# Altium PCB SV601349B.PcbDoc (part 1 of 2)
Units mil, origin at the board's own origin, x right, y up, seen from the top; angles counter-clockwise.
Board outline 3013 x 3112 mil, 4 copper layers (TOP, GND, PWR, BOTTOM), stack 60.36 mil thick; 123 components, 67 nets, 345 pads, 132 vias.
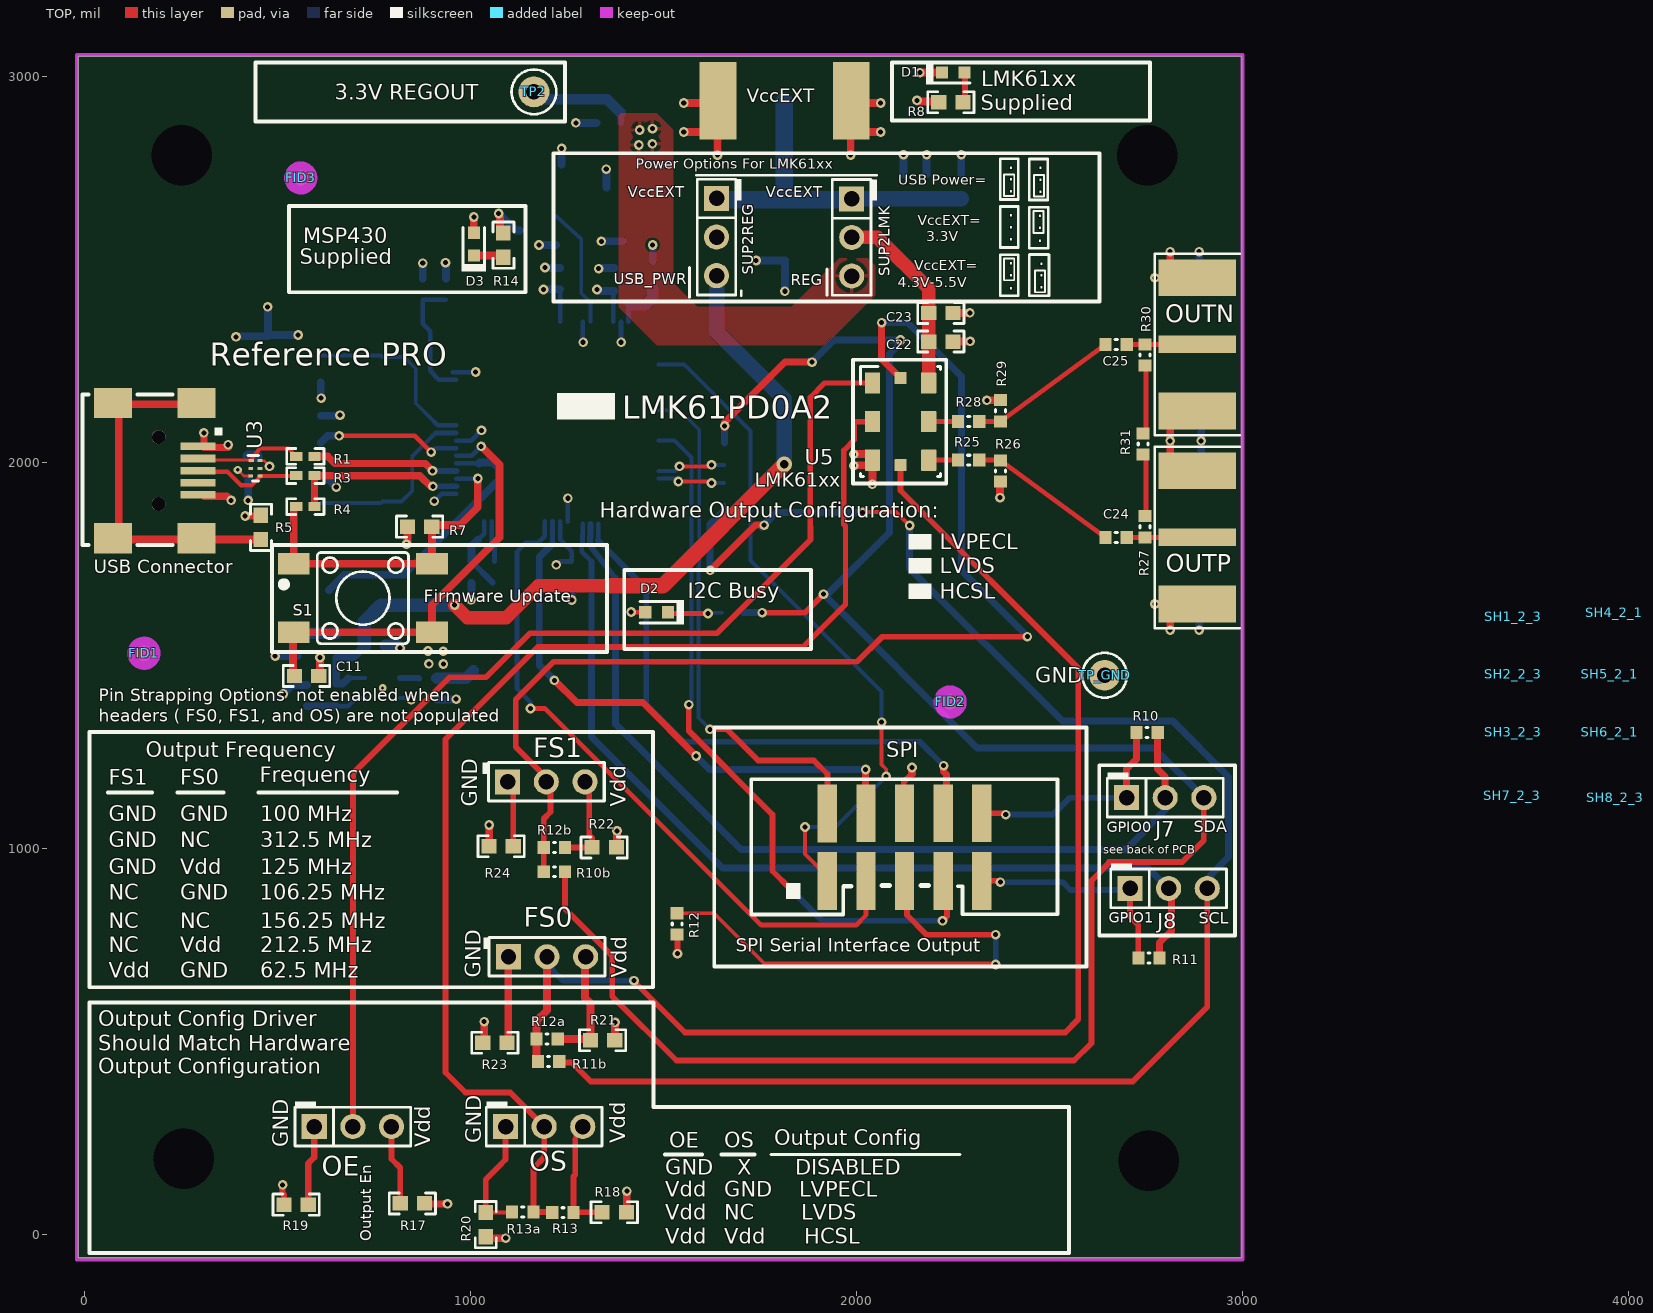
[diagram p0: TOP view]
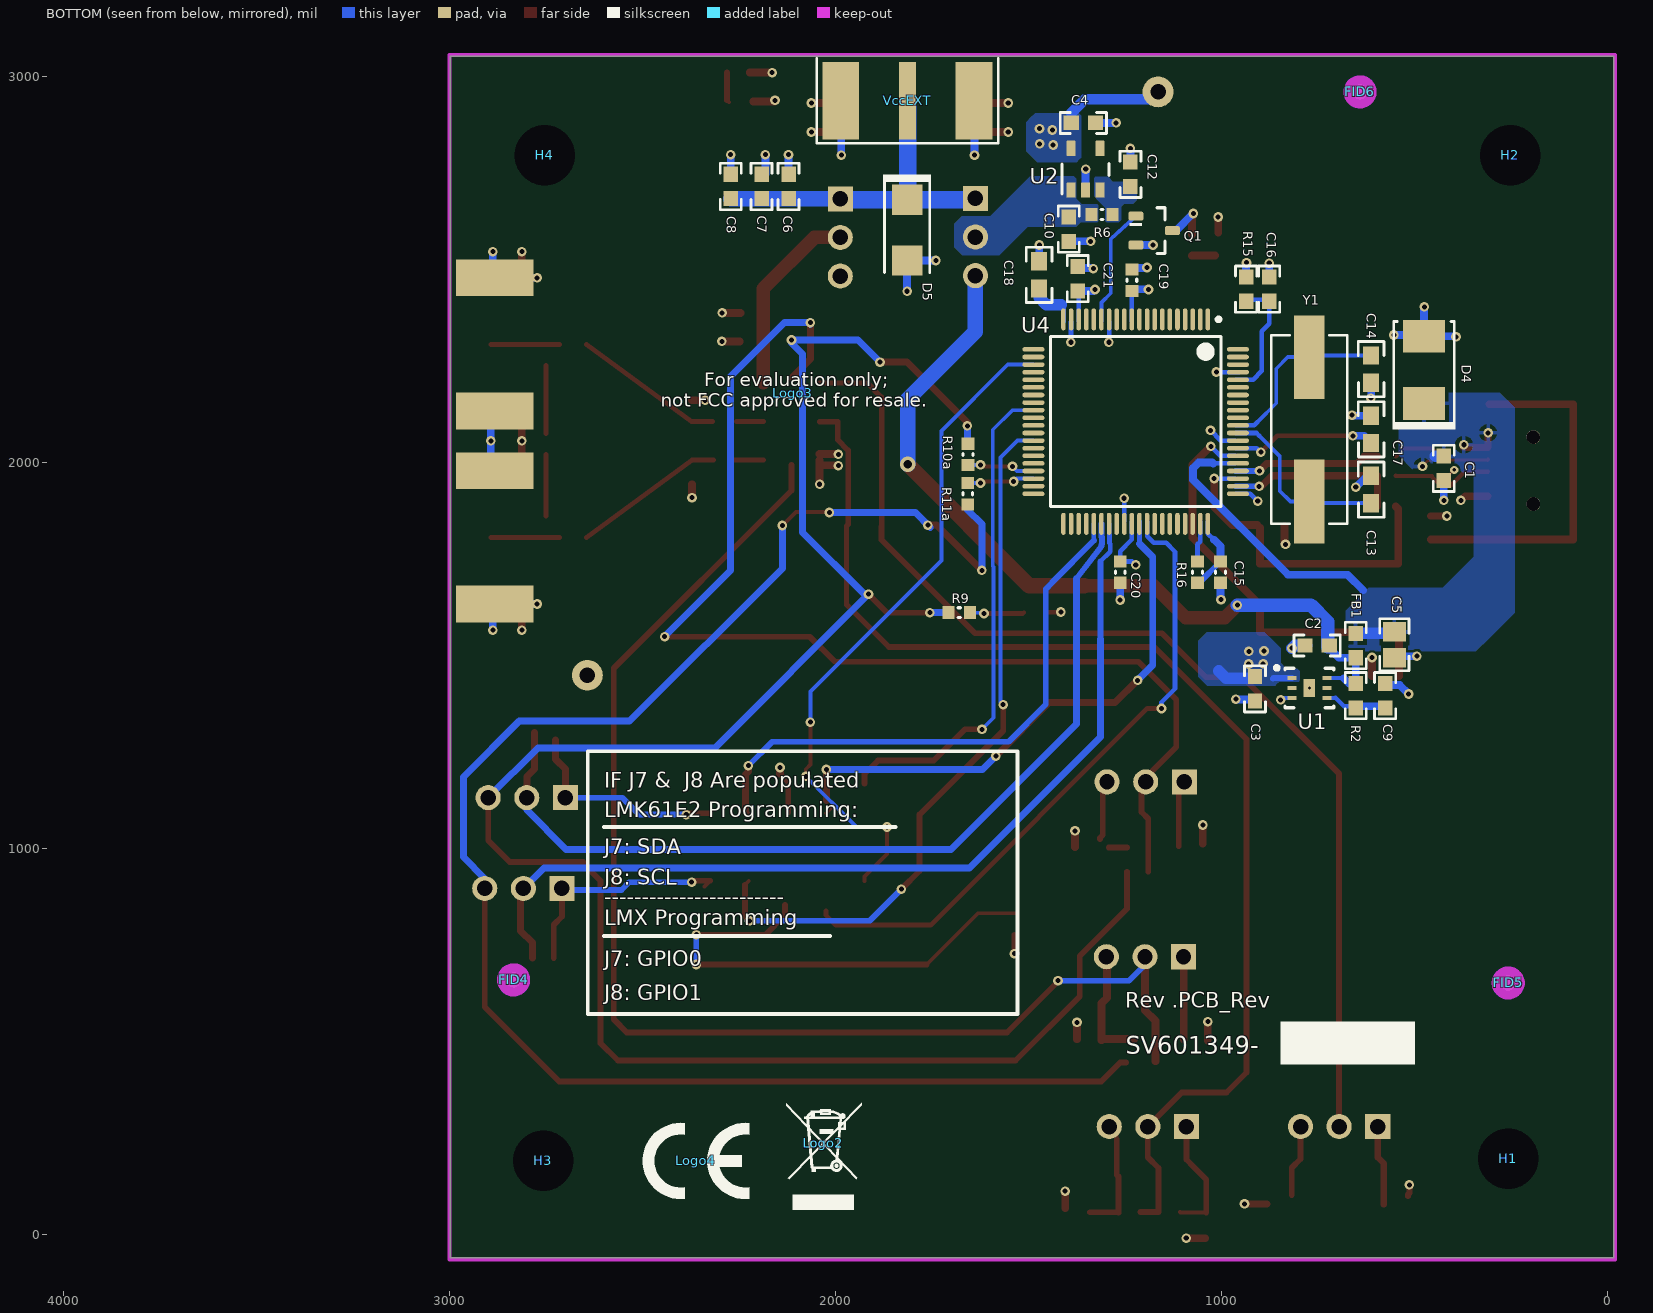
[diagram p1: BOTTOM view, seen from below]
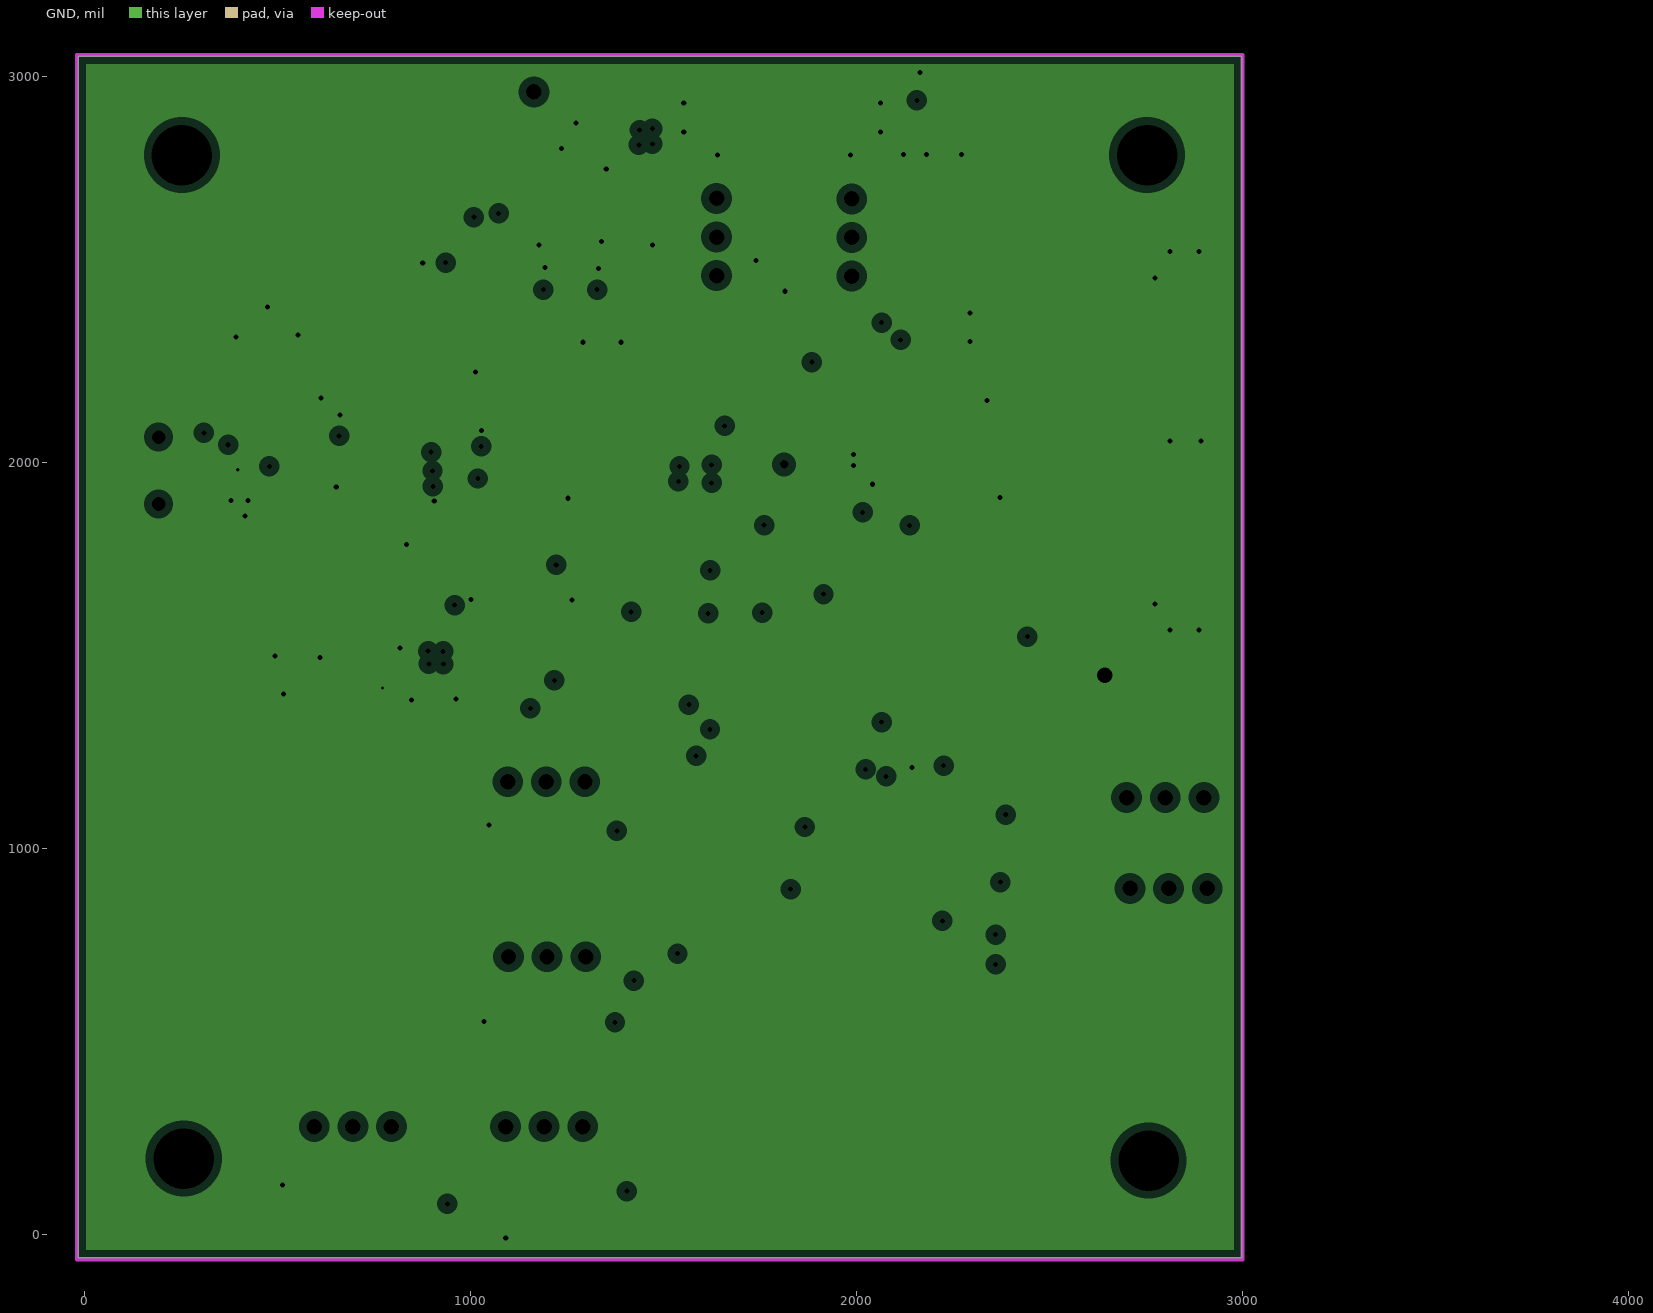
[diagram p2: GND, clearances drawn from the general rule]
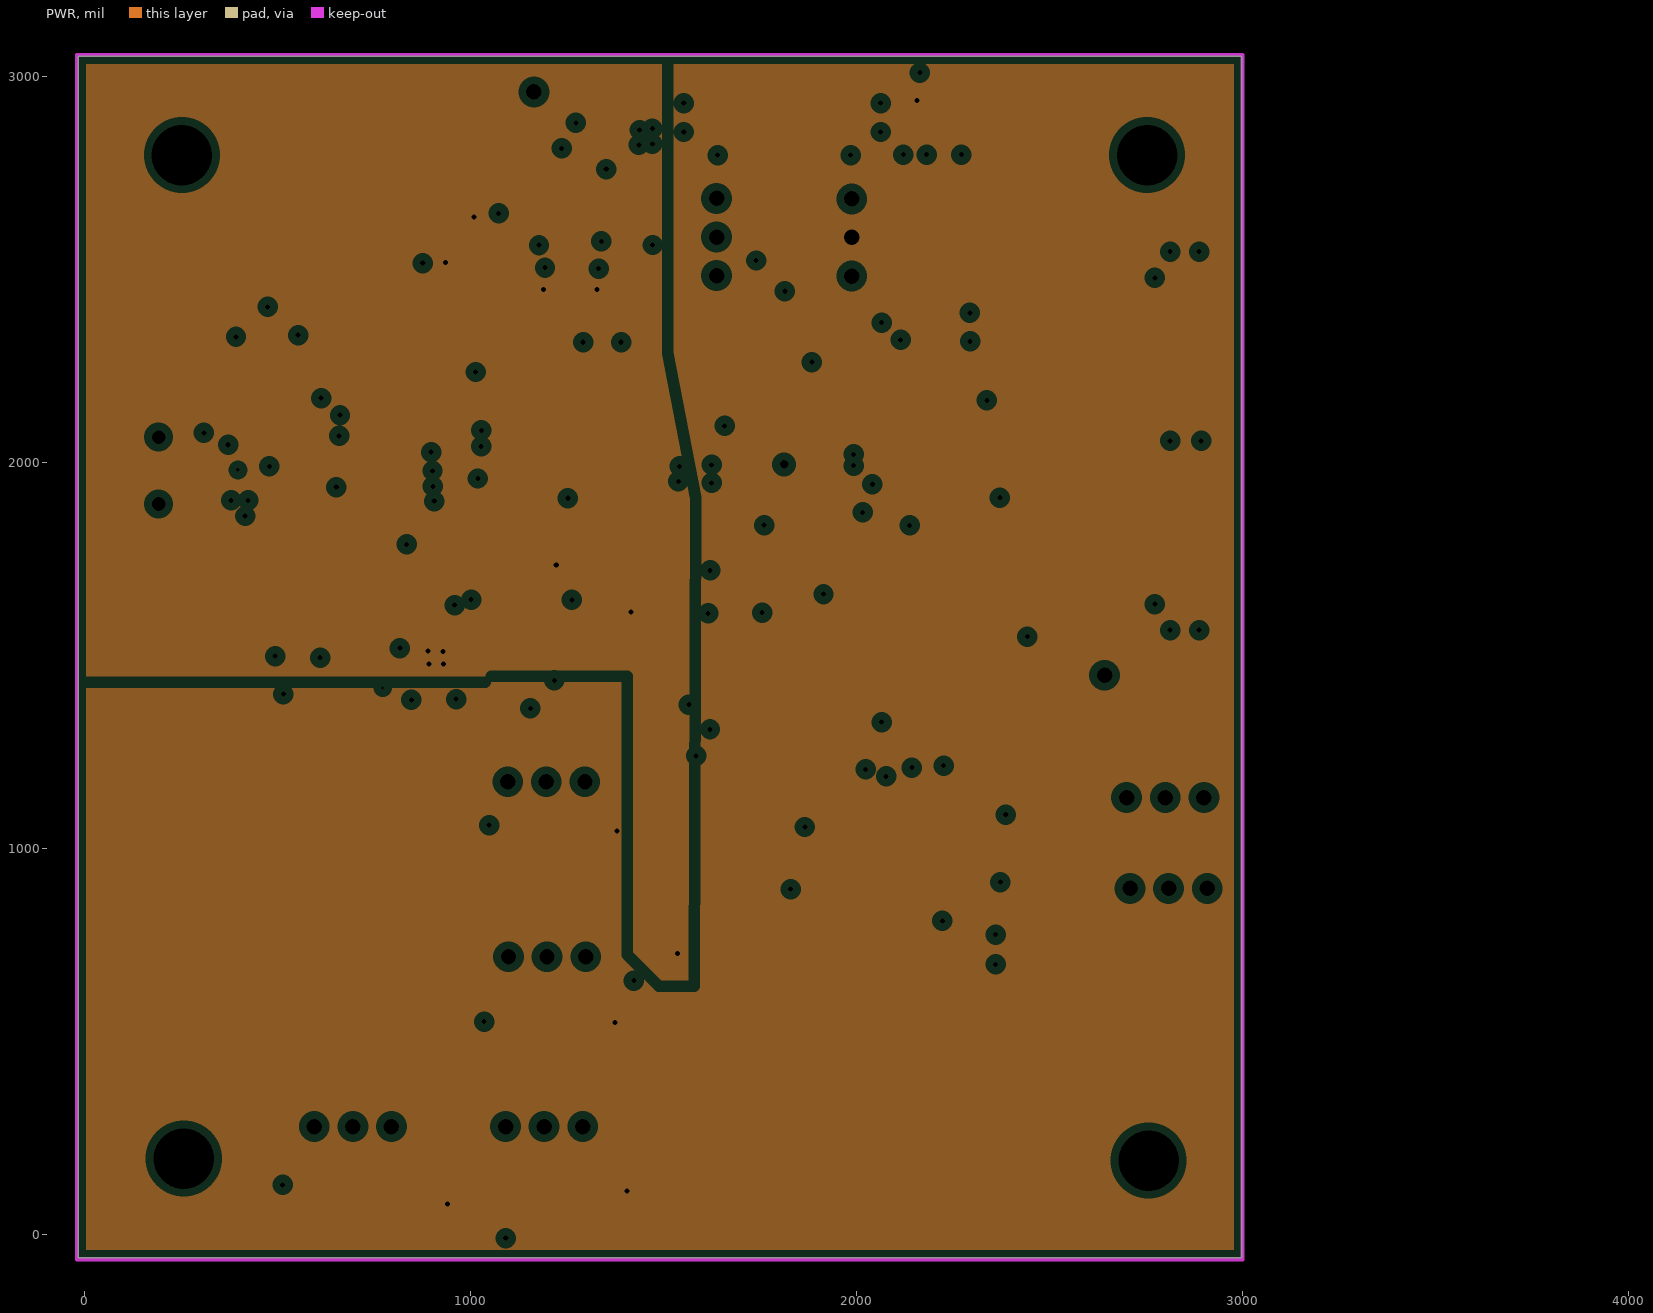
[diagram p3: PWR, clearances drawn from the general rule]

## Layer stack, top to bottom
Top Solder: solder mask 0.8, Solder Resist, Dk 3.5
TOP: signal copper 1.78
Dielectric1: prepreg 8, FR-4, Dk 4.3
GND: plane copper 1.4, net GND
Dielectric2: core 38, FR-4, Dk 4.3
PWR: plane copper 1.4, net (Multiple Nets)
Dielectric3: prepreg 8, FR-4, Dk 4.3
BOTTOM: signal copper 1.78
Bottom Solder: solder mask 0.8, Solder Resist, Dk 3.5

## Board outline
-16,-61 -16,3051 2997,3051 2997,-61

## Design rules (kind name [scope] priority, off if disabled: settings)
AcuteAngle [All] p1: minimum=4.50000000000000E+0001 checktracksonly=FALSE
AssemblyTestPointUsage [All] p1: valid=2
Clearance Clearance_FiducialMark [IsKeepOut and InComponentClass('FiducialMark') vs IsPad and InComponentClass('FiducialMark')] p1: gap=0 ignorepadtopadclearanceinfootprint=FALSE
Clearance Clearance_1 [All] p2: gap=6 ignorepadtopadclearanceinfootprint=FALSE except(0: Arc-Hole Track-Hole SMDPad-Hole THPad-Hole Via-Hole Fill-Hole Poly-Hole Region-Hole Text-Hole)
Clearance Clearance_BoardEdge_MountingHoles [OnCopper and InComponentClass('Mounting Holes') vs IsKeepOut] p3 off: gap=40 ignorepadtopadclearanceinfootprint=FALSE except(0: Arc-Hole Track-Hole SMDPad-Hole THPad-Hole Via-Hole Fill-Hole Poly-Hole Region-Hole Text-Hole)
Clearance Clearance_BoardEdge_Poly [OnCopper and InPoly vs IsKeepOut] p4: gap=25 ignorepadtopadclearanceinfootprint=FALSE except(0: Arc-Hole Track-Hole SMDPad-Hole THPad-Hole Via-Hole Fill-Hole Poly-Hole Region-Hole Text-Hole)
Clearance Clearance_BoardEdge [OnCopper and Not InComponentClass('Logo') and not InComponentClass('FiducialMark') and not InRegion(1000,500,4000,800) and Not IsKeepout vs IsKeepOut] p5 off: gap=50 ignorepadtopadclearanceinfootprint=FALSE except(0: Arc-Hole Track-Hole SMDPad-Hole THPad-Hole Via-Hole Fill-Hole Poly-Hole Region-Hole Text-Hole)
Clearance Clearance_Poly [InPolygon] p6: gap=25 ignorepadtopadclearanceinfootprint=FALSE except(0: Arc-Hole Track-Hole SMDPad-Hole THPad-Hole Via-Hole Fill-Hole Poly-Hole Region-Hole Text-Hole)
Clearance Clearance_KeepOut [OnLayer('Keep-Out Layer')] p7: gap=3 ignorepadtopadclearanceinfootprint=FALSE except(0: Arc-Hole Track-Hole SMDPad-Hole THPad-Hole Via-Hole Fill-Hole Poly-Hole Region-Hole Text-Hole)
ComponentClearance ComponentClearance_Shunt [InComponentClass('Header') vs InComponentClass('Header')] p1: gap=0 collisioncheckmode=3 verticalgap=0 showdistances=FALSE
ComponentClearance ComponentClearance_MountingHoles_FiducialMarks [InComponentClass('Mounting Holes') vs InComponentClass('FiducialMark')] p2: gap=50 collisioncheckmode=3 verticalgap=10 showdistances=FALSE
ComponentClearance ComponentClearance_Logo [InComponentClass('Logo')] p3: gap=50 collisioncheckmode=3 verticalgap=10 showdistances=FALSE
ComponentClearance ComponentClearance_ScrewToNut [(HasFootprint('NY PMS 440 0025 PH')) vs (HasFootprint('Keystone_1902C'))] p4: gap=5 collisioncheckmode=3 verticalgap=10 showdistances=FALSE
ComponentClearance ComponentClearance_MountingHoles [InComponentClass('Mounting Holes')] p5: gap=250 collisioncheckmode=3 verticalgap=100000 showdistances=FALSE
ComponentClearance ComponentClearance_SmallPassives [HasFootprint('0201*') or HasFootprint('0402*') or HasFootprint('0508') or HasFootprint('0603*') or HasFootprint('0612') or HasFootprint('0805*') or HasFootprint('0815*') or HasFootprint('0830*') or HasFootprint('1206*') or HasFootprint('1210*') or HasFootprint('1808*') or HasFootprint('1812*') or HasFootprint('1825*') or HasFootprint('2010*') or HasFootprint('2220*') or HasFootprint('2225*') or HasFootprint('2512*') or HasFootprint('2728*') or HasFootprint('3518*') vs HasFootprint('0201*') or HasFootprint('0402*') or HasFootprint('0508') or HasFootprint('0603*') or HasFootprint('0612') or HasFootprint('0805*') or HasFootprint('0815*') or HasFootprint('0830*') or HasFootprint('1206*') or HasFootprint('1210*') or HasFootprint('1808*') or HasFootprint('1812*') or HasFootprint('1825*') or HasFootprint('2010*') or HasFootprint('2220*') or HasFootprint('2225*') or HasFootprint('2512*') or HasFootprint('2728*') or HasFootprint('3518*')] p6: gap=20 collisioncheckmode=3 verticalgap=10 showdistances=FALSE
ComponentClearance ComponentClearance_THtoSMT [IsThruComponent vs IsSMTComponent] p7: gap=100 collisioncheckmode=3 verticalgap=30 showdistances=FALSE
ComponentClearance ComponentClearance_THtoTH [IsThruComponent vs IsThruComponent] p8: gap=118.11 collisioncheckmode=3 verticalgap=30 showdistances=FALSE
ComponentClearance [All] p9: gap=40 collisioncheckmode=3 verticalgap=10 showdistances=FALSE
DiffPairsRouting [All] p1 off: maxlimit=100 minlimit=10 mostfreqgap=10 toplayer_minwidth=15 toplayer_maxwidth=15 toplayer_prefwidth=15 bottomlayer_minwidth=15 bottomlayer_maxwidth=15 bottomlayer_prefwidth=15 maxuncoupledlength=1000
FabricationTestPointUsage TestPointUsage [All] p1: valid=2 allowmultiple=FALSE
FabricationTestpoint Testpoint [All] p1: side=3 testpointundercomponent=TRUE minsize=40 maxsize=100 preferedsize=60 minholesize=0 maxholesize=40 preferedholesize=32 testpointgrid=1 allowsidetop=TRUE allowsidebottom=TRUE usegrid=TRUE gridtolerance=0.01
FanoutControl Fanout_LCC [IsLCC] p1: bgadir=Out bgaviamode=Centered fanoutstyle=Auto fanoutdirection=Alternating viagrid=1 // Fanout_LCC (Default Rule)
FanoutControl Fanout_BGA [IsBGA] p2: bgadir=Out bgaviamode=Centered fanoutstyle=Auto fanoutdirection=Alternating viagrid=1 // Fanout_BGA (Default Rule)
FanoutControl Fanout_Default [All] p4: bgadir=Out bgaviamode=Centered fanoutstyle=Auto fanoutdirection=Alternating viagrid=1 // Fanout_Default (Default Rule)
FanoutControl Fanout_Small [(CompPinCount < 5)] p5: bgadir=Out bgaviamode=Centered fanoutstyle=Auto fanoutdirection=OutThenIn viagrid=1 // Fanout_Small (Default Rule)
HoleSize [All] p1: absolutevalues=TRUE maxlimit=251 minlimit=7 maxpercent=80.000 minpercent=20.000
MinimumAnnularRing MinimumAnnularRing_ThermalPadVias [IsVia and InAnyComponent] p1: minimumring=5.91
MinimumAnnularRing [All] p2: minimumring=6
MinimumSolderMaskSliver MinimumSolderMaskSliver_Logo [InComponentClass('Logo') vs InComponentClass('Logo')] p1: minsoldermaskwidth=0.7
MinimumSolderMaskSliver [All] p2: minsoldermaskwidth=3.9
PlaneClearance [All] p1: clearance=20
PlaneConnect [All] p1: planeconnectstyle=Relief reliefexpansion=10 reliefentries=4 reliefconductorwidth=10 reliefairgap=10
PolygonConnect PolygonConnect_1 [All vs IsNamedPolygon('Component Side-No Net 1')] p1: connectstyle=Direct reliefconductorwidth=10 reliefentries=4 polygonreliefangle="90 Angle" airgapwidth=10
PolygonConnect [All] p2: connectstyle=Relief reliefconductorwidth=10 reliefentries=4 polygonreliefangle="90 Angle" airgapwidth=10
RoutingVias ThermalPadVias [IsVia and InAnyComponent] p1: holewidth=7.87 width=19.68 viastyle="Through Hole" minholewidth=7.87 minwidth=19.68 maxholewidth=12.99 maxwidth=23.62
RoutingVias [All] p2: holewidth=16 width=34 viastyle="Through Hole" minholewidth=7.87 minwidth=20 maxholewidth=40 maxwidth=65
SMDToCorner [All] p1: distance=30000
SilkToSilkClearance SilkToSilkClearance_Pb-FreeLogo [(HasFootprint('Pb-Free_Overlay_Medium') OR HasFootprint('Pb-Free_Overlay_Small')) vs (HasFootprint('Pb-Free_Overlay_Medium') OR HasFootprint('Pb-Free_Overlay_Small'))] p1: silktosilkclearance=0
SilkToSilkClearance [All] p2: silktosilkclearance=2
SilkToSolderMaskClearance SilkscreenOverComponentPads [IsPad] p1: minsilkscreentomaskgap=3.7 clearancetoexposedcopper=TRUE
SolderMaskExpansion [All] p1: expansion=1.97
Width [All] p1: maxlimit=100 minlimit=6 preferedwidth=10 checkconnectedcopper=TRUE
15 further rules are at their usual default settings.

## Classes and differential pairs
component class SV601349B-S1: C1 C2 C3 C4 C5 C6 C7 C8 C9 C10 C11 C12 C13 C14 C15 C16 C17 C18 C19 C20 C21 D1 D2 D3 D4 D5 FB1 J7 J8 Q1 R1 R2 R3 R4 R5 R6 R7 R8 R9 R10 R10a R11 R11a R12 R14 R15 R16 S1 SH1_2_3 SH2_2_3 SH7_2_3 SH8_2_3 SPI SUP2LMK SUP2REG TP2 TP_GND U1 U2 U3 U4 "USB Connector" "VCC EXT" VccEXT Y1
component class SV601349B-S3: FID1 FID2 FID3 FID4 FID5 FID6 H1 H2 H3 H4 Logo2 Logo3 Logo4 PCB1 ZZ1 ZZ2 ZZ3 ZZ4 ZZ5 ZZ6 ZZ7 ZZ8 ZZ9 ZZ10
component class SV601349B-S2: C22 C23 C24 C25 FS0 FS1 OE OS OUTN OUTP R10b R11b R12a R12b R13 R13a R17 R18 R19 R20 R21 R22 R23 R24 R25 R26 R27 R28 R29 R30 R31 SH3_2_3 SH4_2_1 SH5_2_1 SH6_2_1 Text U5
component class AssemblyNote: ZZ1 ZZ2 ZZ3 ZZ4 ZZ5 ZZ6 ZZ7 ZZ8 ZZ9 ZZ10
component class FiducialMark: FID1 FID2 FID3 FID4 FID5 FID6
component class Header: FS0 FS1 J7 J8 OE OS SUP2LMK SUP2REG
component class Shunt: SH1_2_3 SH2_2_3 SH3_2_3 SH4_2_1 SH5_2_1 SH6_2_1 SH7_2_3 SH8_2_3
differential pair D: +D_P -D_N
differential pair USB: +USB_P -USB_N

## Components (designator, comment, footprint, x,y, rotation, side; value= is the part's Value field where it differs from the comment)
C1 "C0603C104J4RACTU" 0603 424,1984 r90 bottom value=0.1uF
C2 "C1608X5R1A106M080AC" 0603 752,1525 r180 bottom value=10uF
C3 "C1608X5R1A106M080AC" 0603 913,1413 r90 bottom value=10uF
C4 "C0603C105K8PACTU" 0603 1357.4,2878.6 r0 bottom value=1uF
C5 "LMK212BJ226MG-T" 0805 552,1527 r270 bottom value=22uF
C6 "C1608X5R1A106M080AC" 0603 2121,2714 r90 bottom value=10uF
C7 "C0603C105K8PACTU" 0603 2191,2714 r270 bottom value=1uF
C8 "C0603C104J4RACTU" 0603 2271,2714 r270 bottom value=0.1uF
C9 "C0603C104J4RACTU" 0603 576,1395 r270 bottom value=0.1uF
C10 "C0603C105K8PACTU" 0603 1395.1,2603.3 r90 bottom value=1uF
C11 "06035A221FAT2A" 0603 575,1446 r180 top value=220pF
C12 "C0603C104J4RACTU" 0603 1235.6,2745.5 r270 bottom value=0.1uF
C13 "06035A300JAT2A" 0603M 612,1929 r90 bottom value=30pF
C14 "06035A300JAT2A" 0603M 612,2241 r270 bottom value=30pF
C15 "C0603C104J4RACTU" 0603L 1002,1715 r90 bottom value=0.1uF
C16 "C0603C222K5RACTU" 0603 876,2448 r90 bottom value=2200pF
C17 "06035A221FAT2A" 0603M 612,2085 r270 bottom value=220pF
C18 "GRM188R71A474KA61D" 0603M 1472,2485 r270 bottom value=0.47uF
C19 "C0603C104J4RACTU" 0603L 1232,2471 r270 bottom value=0.1uF
C20 "C0603C104J4RACTU" 0603L 1262,1715 r90 bottom value=0.1uF
C21 "C0603C104J4RACTU" 0603 1372,2475 r270 bottom value=0.1uF
C22 "06031C103JAT2A" 0603 2218,2312.2 r0 top value=0.01uF
C23 "C0603C475K8PACTU" 0603 2218,2386.2 r0 top value=4.7uF
C24 "C0603C104J4RACTU" 0603L 2672,1805 r180 top value=0.1uF
C25 "C0603C104J4RACTU" 0603L 2672,2305 r180 top value=0.1uF
D1 "VDD" LED_LTST-C190 2250,3009 r180 top value=Green
D2 "I2C" LED_LTST-C190 1482,1611 r0 top value=Orange
D3 "MSP_LED" LED_LTST-C190 1008.4,2564.5 r270 top value=Green
D4 "1SMB5922BT3G" SMB 475,2239 r90 bottom value=7.5V
D5 "B220A-13-F" SMA 1814,2601 r270 bottom value=20V
FB1 "MPZ1608S600ATAH0" 0603 652,1525 r270 bottom value="60 ohm"
FID1 "Fiducial" Fiducial10-20 154,1505 r0 top
FID2 "Fiducial" Fiducial10-20 2242,1379 r0 top
FID3 "Fiducial" Fiducial10-20 560,2736 r0 top
FID4 "Fiducial" Fiducial10-20 2833,659 r180 bottom
FID5 "Fiducial" Fiducial10-20 257,651 r180 bottom
FID6 "Fiducial" Fiducial10-20 641,2959 r180 bottom
FS0 "FS0" TE_5-146278-3 1198,719 r0 top
FS1 "FS1" TE_5-146278-3 1196,1172 r0 top
H1 "TCBS-6-01" TCBS-6-01 257,196 r90 bottom
H2 "TCBS-6-01" TCBS-6-01 252,2795 r90 bottom
H3 "TCBS-6-01" TCBS-6-01 2756,191 r90 bottom
H4 "TCBS-6-01" TCBS-6-01 2752,2795 r90 bottom
J7 "SDA/GPIO0" TSW-103-07-G-S 2799,1131 r0 top
J8 "SCL/GPIO1" TSW-103-07-G-S 2808,896 r0 top
Logo2 "WEEE logo" WEEE_Minimum 2031,236 r180 bottom
Logo3 "FCC disclaimer" FCC_disclaimer_stacked 2110,2178 r180 bottom
Logo4 "CE Mark" CE_Mark_5mm 2361,190 r180 bottom
OE "OE" TSW-103-07-G-S 695,279 r0 top
OS "OS" TSW-103-07-G-S 1190.5,279 r0 top
OUTN "" Emerson_142-0701-851 2992,2305 r270 top (schematic designator OutN)
OUTP "" Emerson_142-0701-851 2992,1805 r270 top (schematic designator OutP)
Q1 "BSS138" SOT-23 1174.1,2599.8 r180 bottom value=50V
R1 "CRCW040233R0JNED" 0402 572,2015 r180 top value=33
R2 "CRCW060333K0JNEA" 0603 652,1395 r270 bottom value=33k
R3 "CRCW040233R0JNED" 0402 572,1965 r180 top value=33
R4 "CRCW04021K50JNED" 0402 572,1885 r0 top value=1.5k
R5 "CRCW060333K0JNEA" 0603 457,1831 r90 top value=33k
R6 "CRCW060333K0JNEA" 0603L 1309.2,2641.2 r180 bottom value=33k
R7 "CRCW06031M20JNEA" 0603 868,1833 r0 top value=1.2Meg
R8 "CRCW0603510RJNEA" 0603 2244,2932 r180 top value=510
R9 "CRCW0603270RJNEA" 0603L 1679,1610 r180 bottom value=270
R10 "CRCW06030000Z0EA" 0603L 2752,1300 r180 top value=0
R10a "CRCW06030000Z0EA" 0603L 1656,2020 r90 bottom value=0
R10b "CRCW06030000Z0EA" 0603L 1217,939 r180 top value=0
R11 "CRCW06030000Z0EA" 0603L 2757,716 r0 top value=0
R11a "CRCW06030000Z0EA" 0603L 1657,1918 r270 bottom value=0
R11b "CRCW06030000Z0EA" 0603L 1202,448 r180 top value=0
R12 "CRCW06030000Z0EA" 0603L 1535,804 r90 top value=0
R12a "CRCW06030000Z0EA" 0603L 1198,506 r0 top value=0
R12b "CRCW06030000Z0EA" 0603L 1217,1002 r0 top value=0
R13 "CRCW06030000Z0EA" 0603L 1239,56 r0 top value=0
R13a "CRCW06030000Z0EA" 0603L 1135,58 r180 top value=0
R14 "CRCW0603270RJNEA" 0603 1085,2562 r270 top value=270
R15 "CRCW060333K0JNEA" 0603 936,2448 r270 bottom value=33k
R16 "CRCW0603100KJNEA" 0603L 1062,1715 r90 bottom value=100k
R17 "CRCW06031K50JNEA" 0603 849,80 r180 top value=1.5k
R18 "CRCW06031K50JNEA" 0603 1372,57 r180 top value=1.5k
R19 "CRCW06031K50JNEA" 0603 548,77 r180 top value=1.5k
R20 "CRCW06031K50JNEA" 0603 1039,25 r270 top value=1.5k
R21 "CRCW06031K50JNEA" 0603 1342,503 r180 top value=1.5k
R22 "CRCW06031K50JNEA" 0603 1346,1002 r180 top value=1.5k
R23 "CRCW06031K50JNEA" 0603 1063,496 r180 top value=1.5k
R24 "CRCW06031K50JNEA" 0603 1079,1005 r180 top value=1.5k
R25 "CRCW06030000Z0EA" 0603L 2290,2005 r0 top value=0
R26 "CRCW0603150RJNEA" 0603L 2372,1977 r90 top value=150
R27 "CRCW06030000Z0EA" 0603L 2747,1832.56 r270 top value=0
R28 "CRCW06030000Z0EA" 0603L 2290,2105 r0 top value=0
R29 "CRCW0603150RJNEA" 0603L 2372,2133 r90 top value=150
R30 "CRCW06030000Z0EA" 0603L 2747,2277.44 r270 top value=0
R31 "CRCW0603100RFKEA" 0603L 2742,2047 r270 top value=100
S1 "BSL" SW_FSM4JSMA 721,1648 r90 top
SH1_2_3 "969102-0000-DA" SNT-100-BK-G 3700,1600 r0 top value=1x2
SH2_2_3 "969102-0000-DA" SNT-100-BK-G 3700,1450 r0 top value=1x2
SH3_2_3 "969102-0000-DA" SNT-100-BK-G 3700,1300 r0 top value=1x2
SH4_2_1 "969102-0000-DA" SNT-100-BK-G 3962,1610 r180 top value=1x2
SH5_2_1 "969102-0000-DA" SNT-100-BK-G 3950,1450 r0 top value=1x2
SH6_2_1 "969102-0000-DA" SNT-100-BK-G 3950,1300 r0 top value=1x2
SH7_2_3 "969102-0000-DA" SNT-100-BK-G 3698,1136 r180 top value=1x2
SH8_2_3 "969102-0000-DA" SNT-100-BK-G 3964,1131 r180 top value=1x2
SPI "52601-S10-8LF" FCI_52601-S10-8LF 2124,1003 r90 top
SUP2LMK "IC SUP" TSW-103-07-G-S 1987,2582 r270 top
SUP2REG "REG SUP" TSW-103-07-G-S 1637,2583 r270 top
TP2 "VDD REG" Keystone5000 1164,2959 r0 top value=Red
TP_GND "GND" Keystone5001 2642,1448 r0 top value=Black
U1 "LP5900SD-3.3/NOPB" SDB06A 772,1415 r180 bottom
U2 "LP5907MFX-3.3/NOPB" DBV0005A_N 1351.8,2758.6 r90 bottom
U3 "TPD4E004DRYR" DRY0006A 442.68,1984 r0 top
U4 "MSP430F5529IPN" PN0080A_N 1222,2105 r270 bottom
U5 "LMK61PD0A2-SIAT" SIA0008B 2113.57,2105 r0 top
"USB Connector" "1734035-2" CONN_USB-Mini-B-1734035-2 192,1978 r270 top
VccEXT "" Emerson_142-0701-851 1813,3046 r180 bottom
Y1 "ECS-240-20-5PX-TR" XTAL_CSM-7X 772,2085 r90 bottom
ZZ1 "This Assembly Note is for PCB labels only" AssemblyNoteLabel 4776,1449 r0 top
ZZ2 "These assemblies are ESD sensitive, ESD precautions shall be observed." AssemblyNote 4776,1278.6 r0 top
ZZ3 "These assemblies must be clean and free from flux and all contaminants. Use of no clean flux is not acceptable." AssemblyNote 4776,1128.52 r0 top
ZZ4 "These assemblies must comply with workmanship standards IPC-A-610 Class 2, unless otherwise specified." AssemblyNote 4776,978.45 r0 top
ZZ5 "Default Shunt settings: SH1_2-3 means short Pins 2-3 of SUP2REG jumper." AssemblyNote 4776,828.37 r0 top
ZZ6 "Default Shunt settings: SH2_2-3 means short Pins 2-3 of SUP2LMK jumper." AssemblyNote 4776,678.3 r0 top
ZZ7 "Default Shunt settings: SH3_2-3 means short Pins 2-3 of OE jumper." AssemblyNote 4776,528.22 r0 top
ZZ8 "Default Shunt settings: SH4_2-1 means short Pins 1-2 of OS jumper." AssemblyNote 4776,378.15 r0 top
ZZ9 "Default Shunt settings: SH5_2-1 means short Pins 1-2 of FS0 jumper." AssemblyNote 4776,228.07 r0 top
ZZ10 "Default Shunt settings: SH6_2-1 means short Pins 1-2 of FS1 jumper." AssemblyNote 4776,78 r0 top

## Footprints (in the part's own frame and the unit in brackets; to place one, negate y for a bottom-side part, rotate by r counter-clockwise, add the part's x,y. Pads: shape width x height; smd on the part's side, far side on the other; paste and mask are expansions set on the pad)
0402 [mm] "0402 from SM-752 data"
  rect 0.8x0.6 smd: 1(-0.6,0) 2(0.6,0)
  silkscreen extent -1.22,-0.52 1.22,0.52, body extent -0.55,-0.3 0.55,0.3, height 0.6
0603 [mm] "0603 from SM-752 data"
  rect 1x0.95 smd: 1(-0.8,0) 2(0.8,0)
  silkscreen extent -1.52,-0.69 1.52,0.69, body extent -0.87,-0.47 0.87,0.47, height 1
0603L [mm] "0603 from SM-752 data"
  rect 0.8x0.85 smd: 1(-0.7,0) 2(0.7,0)
  silkscreen extent -0.07,-0.33 0.07,0.33, body extent -0.87,-0.47 0.87,0.47, height 1
0603M [mm] "0603 from SM-752 data"
  rect 1.2x1.05 smd: 1(-0.9,0) 2(0.9,0)
  silkscreen extent -1.82,-0.84 1.82,0.84, body extent -0.87,-0.47 0.87,0.47, height 1
0805 [mm] "0805 from SM-752 data"
  rect 1.3x1.5 smd: 1(-0.85,0) 2(0.85,0)
  silkscreen extent -1.72,-0.97 1.72,0.97, body extent -1.1,-0.72 1.1,0.72, height 1.45
AssemblyNote [mil] "Assembly Note"
AssemblyNoteLabel [mil] "Assembly Note for PCB Labels"
CE_Mark_5mm [mil] "Minimum text height for CE Mark"
  silkscreen extent -138,-98 138,98
CONN_USB-Mini-B-1734035-2 [mm] "Tyco Connectivity recommended land pattern"
  rect 0.5x2.3 smd: 1(-1.6,2.6) 2(-0.8,2.6) 3(0,2.6) 4(0.8,2.6) 5(1.6,2.6)
  rect 2x2.5 smd: 6(4.45,2.5) 7(4.45,-3) 8(-4.45,-3) 9(-4.45,2.5)
  round 0.9 hole 0.9 unplated: 10(2.2,0) 11(-2.2,0)
  silkscreen extent -5,-5 4.9,4.19, body extent -4.95,-5.9 4.95,3.3, height 4.1
DBV0005A_N [mm] "SOT23, 5-Leads, Body 2.9x1.6mm, Pitch 0.95mm, Lead Span 2.8mm, IPC Medium Density"
  rrect17% 1x0.6 smd: 1(-1.375,0.95) 2(-1.375,0) 3(-1.375,-0.95) 4(1.375,-0.95) 5(1.375,0.95)
  silkscreen extent -1.63,-1.55 0.38,1.55, body extent -1.42,-1.46 1.42,1.46, height 1.09
DRY0006A [mm] "PSON, 6-Leads, Body 1x1.45mm, Pitch 0.5mm, TI Recommended"
  rect 0.35x0.2 smd: 1(-0.275,0.5)
  rect 0.3x0.2 smd: 2(-0.3,0) 3(-0.3,-0.5) 4(0.3,-0.5) 5(0.3,0) 6(0.3,0.5)
  silkscreen extent -0.5,-0.85 0.2,0.85, body extent -0.53,-0.75 0.53,0.75, height 0.61
Emerson_142-0701-851 [mil] "Johnson Components"
  rect 45x200 smd: 1(0,-110)
  rect 95x200 smd: 2(-172.5,-110) 3(172.5,-110)
  rect 95x200 smd far side: 4(172.5,-110) 5(-172.5,-110)
  silkscreen extent -235,-220 235,0, body extent -190,-195 190,387, height 155
FCC_disclaimer_stacked [mil]
FCI_52601-S10-8LF [mil] "FCI Electronics"
  rect 150x50 smd: 1(-87.5,200) 2(86.5,200) 3(-87.5,100) 4(87.5,100) 5(-87.5,0) 6(87.5,0) 7(-87.5,-100) 8(87.5,-100) 9(-87.5,-200) 10(87.5,-200)
  silkscreen extent -175,-396 176,397, body extent -172,-395 173,395, height 496
Fiducial10-20 [mm]
  round 1 smd mask+0.5: 1(0,0)
  TOP keep-out circle w1.178: c0,0 r0.5
Keystone5000 [mil] "For Keystone 500x miniature loop terminals"
  round 80 hole 40: 1(0,0)
  silkscreen extent -58,-58 58,58, body extent -49,-49 49,49, height 182
Keystone5001 [mil] "For Keystone 500x miniature loop terminals"
  round 80 hole 40: 1(0,0)
  silkscreen extent -58,-58 58,58, body extent -49,-49 49,49, height 182
LED_LTST-C190 [mm] "Lite-On"
  rect 0.8x0.8 smd: 1(-0.75,0) 2(0.75,0)
  silkscreen extent -1.1,-0.8 1.8,0.8, body extent -0.85,-0.45 0.85,0.45, height 0.9
PN0080A_N [mm] "QFP, 80-Leads, Body 12x12mm, Pitch 0.5mm, IPC Medium Density"
  oval 1.45x0.3 smd: 1(-6.725,4.75) 2(-6.725,4.25) 3(-6.725,3.75) 4(-6.725,3.25) 5(-6.725,2.75) 6(-6.725,2.25) 7(-6.725,1.75) 8(-6.725,1.25) 9(-6.725,0.75) 10(-6.725,0.25) 11(-6.725,-0.25) 12(-6.725,-0.75) 13(-6.725,-1.25) 14(-6.725,-1.75) 15(-6.725,-2.25) 16(-6.725,-2.75) 17(-6.725,-3.25) 18(-6.725,-3.75) 19(-6.725,-4.25) 20(-6.725,-4.75) 41(6.725,-4.75) 42(6.725,-4.25) 43(6.725,-3.75) 44(6.725,-3.25) 45(6.725,-2.75) 46(6.725,-2.25) 47(6.725,-1.75) 48(6.725,-1.25) 49(6.725,-0.75) 50(6.725,-0.25) 51(6.725,0.25) 52(6.725,0.75) 53(6.725,1.25) 54(6.725,1.75) 55(6.725,2.25) 56(6.725,2.75) 57(6.725,3.25) 58(6.725,3.75) 59(6.725,4.25) 60(6.725,4.75)
  oval 0.3x1.45 smd: 21(-4.75,-6.725) 22(-4.25,-6.725) 23(-3.75,-6.725) 24(-3.25,-6.725) 25(-2.75,-6.725) 26(-2.25,-6.725) 27(-1.75,-6.725) 28(-1.25,-6.725) 29(-0.75,-6.725) 30(-0.25,-6.725) 31(0.25,-6.725) 32(0.75,-6.725) 33(1.25,-6.725) 34(1.75,-6.725) 35(2.25,-6.725) 36(2.75,-6.725) 37(3.25,-6.725) 38(3.75,-6.725) 39(4.25,-6.725) 40(4.75,-6.725) 61(4.75,6.725) 62(4.25,6.725) 63(3.75,6.725) 64(3.25,6.725) 65(2.75,6.725) 66(2.25,6.725) 67(1.75,6.725) 68(1.25,6.725) 69(0.75,6.725) 70(0.25,6.725) 71(-0.25,6.725) 72(-0.75,6.725) 73(-1.25,6.725) 74(-1.75,6.725) 75(-2.25,6.725) 76(-2.75,6.725) 77(-3.25,6.725) 78(-3.75,6.725) 79(-4.25,6.725) 80(-4.75,6.725)
  silkscreen extent -6.85,-5.6 5.6,5.6, body extent -7,-7 7,7, height 1.56
SDB06A [mm] "SON, 6-Leads, Body 2.2x2.5mm, Pitch 0.65mm, NSC Recommended (SC-70 Land)"
  rect 0.6x0.25 smd paste-0.125 mask+0.051: 1(-1.15,0.65) 2(-1.15,0) 3(-1.15,-0.65) 4(1.15,-0.65) 5(1.15,0) 6(1.15,0.65)
  rect 0.75x1.2 smd paste-0.6 mask+0.051: 7(0,0)
  silkscreen extent -2.28,-1.3 1.6,1.45, body extent -1.3,-1.15 1.3,1.15, height 0.8
SIA0008B [mm] "SIP 8-Leads, Body 5x7mm"
  rrect17% 1x0.6 on Top Paste: 1(-1.85,2.14) 1(-1.85,2.94) 2(-1.85,-0.4) 2(-1.85,0.4) 3(-1.85,-2.94) 3(-1.85,-2.14) 4(1.85,-2.94) 4(1.85,-2.14) 5(1.85,-0.4) 5(1.85,0.4) 6(1.85,2.14) 6(1.85,2.94)
  rrect10% 1x1.4 smd paste-0.5: 1(-1.85,2.54) 2(-1.85,0) 3(-1.85,-2.54) 4(1.85,-2.54) 5(1.85,0) 6(1.85,2.54)
  rrect12% 0.8x0.8 smd: 7(0,2.865) 8(0,-2.865)
  silkscreen extent -2.64,-3.63 2.64,3.63, body extent -2.56,-3.56 2.56,3.56, height 1.13
SMA [mm] "Molded Diode, 2-Leads, Body 4.3x2.6mm, IPC Medium Density, based on OnSemi component dimensions and land pattern"
  rect 2x2 smd: 1(-2,0) 2(2,0)
  silkscreen extent -3.66,-1.57 2.79,1.57, body extent -2.6,-1.3 2.6,1.3, height 2.42
SMB [mil] "Molded Diode, 2-Leads, Body 5.4x3.6mm, IPC Medium Density, based on OnSemi component dimensions"
  rect 85x107.99 smd: 1(-87.01,0) 2(87.01,0)
  silkscreen extent -155,-82 125,82, body extent -106,-71 106,71, height 91
SNT-100-BK-G [mil] "Samtec STEP model"
  round 1 on Mech3: 0(0,0)
  body extent -100,-50 100,50, height 344
SOT-23 [mm] "SOT23, 3-Leads, Body 2.9x1.3mm, Pitch 0.95mm, Lead Span 2.5mm, IPC Medium Density"
  rrect50% 1x0.6 smd: 1(-1.2,0.95) 2(-1.2,-0.95) 3(1.2,0)
  silkscreen extent -1.62,-1.5 0.7,1.5, body extent -1.16,-1.45 1.21,1.45, height 1
SW_FSM4JSMA [mm] "Alcoswitch"
  rect 1.4x2.1 smd: 1(2.25,4.55) 2(2.25,-4.55) 3(-2.25,4.55) 4(-2.25,-4.55)
  silkscreen extent -3,-3 3,5.4, body extent -3,-5 3,5, height 5.1
TCBS-6-01 [mil] "Richco Plastics"
  round 60 hole 157 unplated: 1(0,0)
  body extent -180,-156 180,156, height 375
TE_5-146278-3 [mm] "TE CONNECTIVITY"
  rect 1.65x1.65 hole 1: 1(-2.54,0)
  round 1.65 hole 1: 2(0,0) 3(2.54,0)
  silkscreen extent -4.19,-1.27 3.81,1.27, body extent -3.68,-1.17 3.68,1.17, height 8.13
TSW-103-07-G-S [mm] "Samtec 100mil, 1x3, 230 mil above insulator"
  rect 1.65x1.65 hole 1.016: 1(-2.54,0)
  round 1.65 hole 1.016: 2(0,0) 3(2.54,0)
  silkscreen extent -3.81,-1.27 3.81,1.65, body extent -3.81,-1.27 3.81,1.27, height 8.38
WEEE_Minimum [mil] "WEEElie bin"
  silkscreen extent -95,-172 99,104
XTAL_CSM-7X [mm] "ECS"
  rect 5.5x2 smd: 1(-4.75,0) 2(4.75,0)
  silkscreen extent -6.2,-2.5 6.2,2.5, body extent -5.95,-2.4 5.95,2.4, height 4.3

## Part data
C1 C8 C9 C12 C15 C19 C20 C21 C24 C25: "CAP, CERM, 0.1uF, 16V, +/-5%, X7R, 0603", Cap_Case=0603, Manufacturer=Kemet, Supplier Part Number 1=399-1097-1-ND, TempCo=X7R, Tolerance_%=5, Value1=Unknown, Value2=16V, ValueDisplayed=0.1µF
C2 C3 C6: "CAP, CERM, 10 µF, 10 V, +/- 20%, X5R, 0603", Cap_Case=0603, Manufacturer=TDK, Supplier Part Number 1=445-6853-1-ND, TempCo=X5R, Tolerance_%=20, Value1="0.0078 ohm", Value2=10V, ValueDisplayed=10µF
C4 C7 C10: "CAP, CERM, 1uF, 10V, +/-10%, X5R, 0603", Cap_Case=0603, Dielectric=X5R, DigiKeyPartNumber=399-3118-1-ND, Manufacturer=Kemet, Tolerance_%=10, Value1=?, Value2=10V, ValueDisplayed=1µF
C5: "CAP, CERM, 22uF, 10V, +/-20%, X5R, 0805", Cap_Case=0805, Manufacturer="Taiyo Yuden", Supplier Part Number 1=587-1958-1-ND, TempCo=X5R, Tolerance_%=20, Value1=Unknown, Value2=10V, ValueDisplayed=22µF
C11 C17: "CAP, CERM, 220pF, 50V, +/-1%, C0G/NP0, 0603", Alternate Manufacturer=-, Cap_Case=0603, Manufacturer=AVX, Supplier Part Number 1=478-3719-1-ND, TempCo=C0G/NP0, Tolerance_%=1, Value1="0.083 ohm", Value2=50V, ValueDisplayed=220pF
C13 C14: "CAP, CERM, 30 pF, 50 V, +/- 5%, C0G/NP0, 0603", Cap_Case=0603, Manufacturer=AVX, Supplier Part Number 1=478-7917-1-ND, TempCo=C0G/NP0, Tolerance_%=5, Value1="0.232 ohm", Value2=50V, ValueDisplayed=30pF
C16: "CAP, CERM, 2200pF, 50V, +/-10%, X7R, 0603", Cap_Case=0603, Manufacturer=Kemet, Supplier Part Number 1=399-1085-1-ND, TempCo=X7R, Tolerance_%=10, Value1=Unknown, Value2=50V, ValueDisplayed=2200pF
C18: "CAP, CERM, 0.47uF, 10V, +/-10%, X7R, 0603", Alternate Manufacturer=-, Cap_Case=0603, Manufacturer=MuRata, Supplier Part Number 1=GRM188R71A474KA61D-ND, TempCo=X7R, Tolerance_%=10, Value1=?, Value2=10V, ValueDisplayed=0.47µF
C22: "CAP, CERM, 0.01 µF, 100 V, +/- 5%, X7R, 0603", Cap_Case=0603, Manufacturer=AVX, Supplier Part Number 1=478-3700-1-ND, TempCo=X7R, Tolerance_%=5, Value1="0.098 ohm", Value2=100V, ValueDisplayed=0.01µF
C23: "CAP, CERM, 4.7 µF, 10 V, +/- 10%, X5R, 0603", Cap_Case=0603, Manufacturer=Kemet, Supplier Part Number 1=399-5503-1-ND, TempCo=X5R, Tolerance_%=10, Value1="0.006 ohm", Value2=10V, ValueDisplayed=4.7µF
D1 D3: library part LTST-C190GKT, "LED, Green, SMD", Color=green, Manufacturer=Lite-On, Power_TotalModule=0.1, Supplier Part Number 1=160-1183-1-ND, Value1=0.1W, Value2=2.1V
D2: library part LTST-C190KFKT, "LED, Orange, SMD", Color=orange, Manufacturer=Lite-On, Power_TotalModule=0.075, Supplier Part Number 1=160-1434-1-ND, Value1=0.075W, Value2=2V
D4: "Diode, Zener, 7.5V, 550mW, SMB", Manufacturer="ON Semiconductor", Power_W=0.55, Supplier Part Number 1=863-1SMB5922BT3G, Value1=0.55W
D5: "Diode, Schottky, 20V, 2A, SMA", Manufacturer="Diodes Inc.", Supplier Part Number 1=B220A-FDICT-ND, Value1=2A, Value2=0.5V
FB1: "Ferrite Bead, 60 ohm @ 100 MHz, 3.5 A, 0603", Manufacturer=TDK, Supplier Part Number 1=445-1563-1-ND, Value1="0.02 ohm", Value2=3.5A
FID1 FID2: "Fiducial mark.  There is nothing to buy or mount.", Manufacturer=N/A
FID3 FID4 FID5 FID6: library part CMP-0077181-1, "Fiducial mark.  There is nothing to buy or mount.", Manufacturer=N/A
FS0 FS1: library part 5-146278-3, "Header, 100mil, 3x1, Tin, TH", Manufacturer="TE Connectivity", Supplier Part Number 1=5-146278-3-ND
H1 H2 H3 H4: "HEX STANDOFF SPACER, 9.53 mm", Manufacturer="Richco Plastics", Supplier Part Number 1=TCBS-6-01-ND
J7 J8 OE OS SUP2LMK SUP2REG: library part TSW-103-07-G-S, "Header, 100mil, 3x1, Gold, TH", Manufacturer=Samtec, Supplier Part Number 1=SAM1029-03-ND
Logo2: library part CMP-0074769-1
Logo3: library part FCC_disclaimer, "FCC_disclaimer"
Logo4: library part CMP-0074844-1
OUTN OUTP VccEXT: library part 142-0701-851, "Connector, End launch SMA, 50 ohm, SMT", Manufacturer="Emerson Network Power", Supplier Part Number 1=J658-ND
Q1: "MOSFET, N-CH, 50V, 0.22A, SOT-23", Alternate Manufacturer=None, Manufacturer="Fairchild Semiconductor", Supplier Part Number 1=BSS138CT-ND, Value1="6 ohm", Value2="1.7 nC"
R1 R3: "RES, 33 ohm, 5%, 0.063W, 0402", Alternate Manufacturer=-, Manufacturer=Vishay-Dale, Power_W=0.063, Supplier Part Number 1=541-33JCT-ND, TempCo="200 ppm/C", Tolerance_%=5, Value1=5%, Value2=0.063W, Value_Code=33R0
R2 R5 R6 R15: "RES, 33k ohm, 5%, 0.1W, 0603", Manufacturer=Vishay-Dale, Power_W=0.1, Supplier Part Number 1=541-33KGCT-ND, TempCo="200 ppm/C", Tolerance_%=5, Value1=5%, Value2=0.1W, Value_Code=33k0
R4: "RES, 1.5k ohm, 5%, 0.063W, 0402", Manufacturer=Vishay-Dale, Power_W=0.063, Supplier Part Number 1=541-1.5KJCT-ND, TempCo="200 ppm/C", Tolerance_%=5, Value1=5%, Value2=0.063W, Value_Code=1k50
R7: "RES, 1.2Meg ohm, 5%, 0.1W, 0603", Alternate Manufacturer=-, Manufacturer=Vishay-Dale, Power_W=0.1, Supplier Part Number 1=541-1.2MGCT-ND, TempCo="200 ppm/C", Tolerance_%=5, Value1=5%, Value2=0.1W, Value_Code=1M20
R8: "RES, 510, 5%, 0.1 W, 0603", Manufacturer=Vishay-Dale, Power_W=0.1, Supplier Part Number 1=541-510GCT-ND, TempCo="200 ppm/C", Tolerance_%=5, Value1=5%, Value2=0.1W, Value_Code=510R, ValueDisplayed=510
R9 R14: "RES, 270 ohm, 5%, 0.1W, 0603", Manufacturer=Vishay-Dale, Power_W=0.1, Supplier Part Number 1=541-270GCT-ND, TempCo="200 ppm/C", Tolerance_%=5, Value1=5%, Value2=0.1W, Value_Code=270R
R10 R10a R10b R11 R11a R11b R12 R12a R12b R13 R13a R25 R27 R28 R30: "RES, 0 ohm, 5%, 0.1W, 0603", Manufacturer=Vishay-Dale, Power_W=0.1, Supplier Part Number 1=541-0.0GCT-ND, TempCo="200 ppm/C", Tolerance_%=5, Value1=5%, Value2=0.1W, Value_Code=0000
R16: "RES, 100k ohm, 5%, 0.1W, 0603", Manufacturer=Vishay-Dale, Power_W=0.1, Supplier Part Number 1=71-CRCW0603J-100K-E3, TempCo="200 ppm/C", Tolerance_%=5, Value1=5%, Value2=0.1W, Value_Code=100k
R17 R18 R19 R20 R21 R22 R23 R24: "RES, 1.5k ohm, 5%, 0.1W, 0603", Manufacturer=Vishay-Dale, Power_W=0.1, Supplier Part Number 1=541-1.5KGCT-ND, TempCo="200 ppm/C", Tolerance_%=5, Value1=5%, Value2=0.1W, Value_Code=1k50
R26 R29: "RES, 150, 5%, 0.1 W, 0603", Manufacturer=Vishay-Dale, Power_W=0.1, Supplier Part Number 1=541-150GCT-ND, TempCo="200 ppm/C", Tolerance_%=5, Value1=5%, Value2=0.1W, Value_Code=150R, ValueDisplayed=150
R31: "RES, 100, 1%, 0.1 W, 0603", Manufacturer=Vishay-Dale, Power_W=0.1, Supplier Part Number 1=541-100HCT-ND, TempCo="100 ppm/C", Tolerance_%=1, Value1=1%, Value2=0.1W, Value_Code=100R, ValueDisplayed=100
S1: library part 4-1437565-1, "Switch, Tactile, SPST-NO, 0.05A, 12V, SMT", CurrentRating_mA=50, Manufacturer="TE Connectivity", Supplier Part Number 1=450-1129-ND
SH1_2_3 SH2_2_3 SH3_2_3 SH4_2_1 SH5_2_1 SH6_2_1 SH7_2_3 SH8_2_3: "Shunt, 100mil, Gold plated, Black", Alternate Manufacturer=Samtec, Alternate PartNumber=SNT-100-BK-G, Manufacturer=3M, Supplier Part Number 1=3M9580-ND
SPI: "Header (shrouded), 100mil, 5x2, Gold, SMT", Manufacturer=FCI, Supplier Part Number 1=609-3593-ND
TP2: library part 5000, "Test Point, Miniature, Red, TH", Manufacturer=Keystone, Supplier Part Number 1=5000K-ND
TP_GND: library part 5001, "Test Point, Miniature, Black, TH", Manufacturer=Keystone, Supplier Part Number 1=5001K-ND
U1: "Ultra Low Noise, 150mA Linear Regulator for RF/Analog Circuits Requires No Bypass Capacitor, 6-pin LLP, Pb-Free", Manufacturer="Texas Instruments", PackageTopMarking=XTT*L16, PowerWise=N, Supplier Part Number 1=LP5900SD-3.3TR-ND
U2: "ULTRA LOW-NOISE, 250-mA LINEAR REGULATOR FOR RF AND ANALOG CIRCUITS REQUIRES NO BYPASS CAPACITOR, DBV0005A", Alternate Manufacturer="Texas Instruments"
U3: "ESD-Protection Array for High-Speed Data Interfaces, 4 Channels, -40 to +85 degC, 6-pin SON (DRY), Green (RoHS & no Sb/Br)", Alternate Manufacturer="Texas Instruments", Alternate PartNumber=Equivalent, Breakdown Voltage(Min)(V)=6, IO Capacitance(Typ)(pF)=1.6, IO Leakage Current(nA)=1, Supplier Part Number 1=296-23618-2-ND
U4: "Mixed Signal MicroController, PN0080A", Alternate Manufacturer=None, Frequency(MHz)=25, Manufacturer="Texas Instruments", Supplier Part Number 1=296-25427-ND, Temp Sensor=Yes
U5: library part CMP-0075886-1, "Ultra-Low Jitter Pin Selectable, Differential Oscillator, +/-50ppm, SIA0008B (QFM-8)", Alternate Manufacturer="Texas Instruments"
"USB Connector": "Connector, Receptacle, Mini-USB Type B, R/A, Top Mount SMT", Manufacturer="TE Connectivity", Supplier Part Number 1=A31727CT-ND
Y1: "Crystal, 24.000MHz, 20pF, SMD", Frequency=24MHz, Frequency Stability=±50ppm, Manufacturer="ECS Inc.", Supplier Part Number 1=XC1255CT-ND
ZZ1: library part CMP-0003616-3
ZZ2: library part CMP-0077236-1
ZZ3: library part CMP-0077237-1
ZZ4 ZZ5 ZZ6 ZZ7 ZZ8 ZZ9 ZZ10: library part CMP-0077238-1

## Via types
v1: diameter 25, hole 13, TOP to BOTTOM, 129 vias
v2: diameter 19.68, hole 7.87, TOP to BOTTOM, tented top, 1 vias
v3: diameter 40, hole 22, TOP to BOTTOM, 1 vias
v4: diameter 21, hole 9, TOP to BOTTOM, 1 vias

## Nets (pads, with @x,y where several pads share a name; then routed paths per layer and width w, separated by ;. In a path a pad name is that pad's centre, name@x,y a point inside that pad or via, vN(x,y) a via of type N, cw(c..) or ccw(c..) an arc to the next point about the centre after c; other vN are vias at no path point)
ADD/OS: OS.2 R13.1 R13a.1 U5.2@2040.74,2105 | length 3173.3
  TOP w10: R13.1@1209.44,58 R13.1@1211.44,56
  TOP w14: 1861,1521 1971,1631 1971,1834 1966.5,1838.5 1966.5,2030.56 1994,2058.06 1994,2105 U5.2@2040.74,2105
  TOP w15: R13.1@1209.44,58 R13a.1@1162.56,58 1162.56,171.56 1190.5,199.5 OS.2@1190.5,279 1102.5,367 987,367 935,419 935,1282 1174,1521 1861,1521
D_N: R1.1 U4.64 | length 383.6
  TOP w19: R1.1@595.62,2015 630,2015 632,2013 632,2012.32 647.82,1996.5 882.2,1996.5 v1(901.3,1977.4)
  BOTTOM w15: v1(901.3,1977.4) 901.65,1977.05 U4.64@963.14,1977.05
D_P: R3.1 R4.2 U4.62 | length 455.6
  TOP w19: R4.2@595.62,1885 R3.1@595.62,1961.38 ; R3.1@595.62,1965 868.45,1965 896.25,1937.2 v1(902.2,1937.2)
  BOTTOM w15: v1(902.2,1937.2) 902.68,1937.68 U4.62@963.14,1937.68
EXT3.3V_EN: R16.2 U4.59 | length 106.6
  BOTTOM w12: U4.59@1054.68,1846.14 1054.68,1794.32 1062,1787 R16.2@1062,1742.56
EXT3.3V_FAULT: C15.2 R16.1 U4.60 | length 195.2
  BOTTOM w12: 1018.9,1798.8 1034.99,1814.89 U4.60@1034.99,1846.14
  BOTTOM w15: C15.2@1002,1742.56 R16.1@1057.12,1687.44
  BOTTOM w20: C15.2@1002,1742.56 1002,1781.9 1018.9,1798.8
EXT5V_EN: U4.57
EXT5V_FAULT: U4.58
EXTIN: C6.1 C7.2 C8.2 D5.1 SUP2LMK.1 SUP2REG.1 VccEXT.1 | length 894.7
  BOTTOM w30: D5.1@1812,2681.74 D5.1@1814,2679.74
  BOTTOM w40: SUP2LMK.1@1987,2682 1987.5,2682.5 2111,2682.5 C7.2@2191,2682.5 C8.2@2271,2682.5
  BOTTOM w45: SUP2REG.1@1637,2688 1645.26,2679.74 D5.1@1814,2679.74 1984.74,2679.74 SUP2LMK.1@1987,2682 ; D5.1@1812,2681.74 VccEXT.1@1812,2935
FS0: FS0.2 R11b.2 R12a.1 U5.8 | length 3402.4
  TOP w10: R11b.2@1170.44,448 R11b.2@1173.44,445
  TOP w15: v1@1418,660 1555,523 2540,523 2574,557 2574,1466 2113.57,1926.43 U5.8@2113.57,1992.2
  TOP w20: R11b.2@1170.44,448 R12a.1@1170.44,506 1170.44,552.44 1198,580 FS0.2@1198,719
  BOTTOM w15: FS0.2@1198,719 1198,698 1239,657 v1(1423,657)
FS1: FS1.2 R10b.2 R12b.1 U5.7 | length 3074.3
  TOP w15: R10b.2@1189.44,939 R12b.1@1189.44,1002 1189.44,1076.44 1207,1094 1207,1172 1117,1262 1117,1385 1215,1483 2001,1483 2066,1548 v1(2442,1548)
  TOP w18: v1(2064.57,2361.43) 2064.57,2266.8 U5.7@2113.57,2217.8
  BOTTOM w10: v1@2063,2367 2063,2354 v1@2064,2353 ; v1@2441,1545 v1@2444,1542
  BOTTOM w18: v1(2064.57,2361.43) 2130.98,2361.43 2271,2221.41 2271,1719 v1(2442,1548)
GND: "USB Connector.5" C1.1 C2.1 C3.1 C4.1 C5.2 C6.2 C7.1 C8.1 C9.1 C10.1 C11.1 C12.1 C13.2 C14.2 C15.1 C16.2 C17.1 C18.1 C19.1 C20.1 C21.1 C22.2 C23.2 D1.2 D4.2 D5.2 OUTN.2 OUTN.3 OUTN.4 OUTN.5 OUTP.2 OUTP.3 OUTP.4 OUTP.5 Q1.2 R5.2 R7.1 R19.2 R20.2 R23.2 R24.2 R26.1 R29.2 SPI.6 TP_GND.1 U1.3 U1.7 U2.2 U3.3 U4.14 U4.19 U4.49 U4.61 U4.68 U4.77 U5.3@2040.74,2005 VccEXT.2 VccEXT.3 VccEXT.4 VccEXT.5 | length 4676.6
  TOP w7: v4(397,1980) 412.68,1964.32 U3.3@430.87,1964.32
  TOP w10: SPI.6@2122,1092.5 SPI.6@2124,1090.5
  TOP w15: 513,107 516.5,103.5 516.5,98.7 ; SPI.6@2122,1092.5 2122,1171.79 2143,1192.79
  TOP w16: 513,107 v1(513,128)
  TOP w19: 309.36,1912.01 368.99,1912.01 v1(380,1901) ; v1(415.9,1860.5) R5.2@458,1860.5
  TOP w20: C11.1@610,1446 v1(610,1493.8) ; v1(834,1787) 833.4,1787 833,1787.4 836.5,1790.9 R7.1@836.5,1833 ; R23.2@1035,502.3 v1(1035,551) ; R20.2@1042.3,-10 v1(1091,-10) ; R24.2@1048,1011.3 v1(1048,1060) ; v1(1552,2855) VccEXT.4@1634.5,2855 ; v1(1552,2930) VccEXT.4@1634.5,2930 ; v1(1639.5,2795) VccEXT.4@1639.5,2925 ; v1(1984.5,2795) VccEXT.5@1984.5,2930 ; VccEXT.5@1985.5,2855 v1(2062,2855) ; VccEXT.5@1989.5,2930 v1(2062,2930) ; v1@1992,1992 U5.3@2040.74,1992 ; v1@1992,2021 U5.3@2040.74,2021 ; v1(2040.3,1942.7) 2040.74,1943.14 U5.3@2040.74,1992 ; U5.3@2040.74,2005 U5.3@2040.74,1992 ; 2143,1192.79 v1(2143,1209) ; v1(2163.6,3008.6) 2164,3009 D1.2@2221.47,3009 ; C23.2@2245.51,2386.2 2292.52,2386.2 v1(2292.92,2386.6) ; C22.2@2247.51,2312.2 2293.02,2312.2 v1(2293.82,2313) ; v1@2337.56,2160.56 R29.2@2372,2160.56 ; v1(2371,1908) R26.1@2371,1942.56 ; v1(2772,1632.5) OUTP.3@2812,1632.5 ; v1(2772,2477.5) OUTN.2@2882,2477.5 ; v1(2812,1565) OUTP.3@2812,1632.5 ; OUTP.3@2812,1633 OUTP.3@2812,1632.5 ; OUTP.2@2812,1979 v1(2812,2055) OUTN.3@2812,2131.5 ; OUTN.2@2812,2482.5 v1(2812,2545) ; OUTP.3@2892,1632.5 OUTP.3@2812,1632.5
  BOTTOM w10: U1.3@817.28,1389.41 841.49,1389.41 v1(846.5,1384.4)
  BOTTOM w12: v1(905.8,1898.8) 924.99,1917.99 U4.61@963.14,1917.99 ; U4.77@953.51,2233.1 1013.45,2233.1 v1(1013.07,2233.47) ; U4.68@963.14,2055.79 1001.29,2055.79 1027.9,2082.4 v1(1028.1,2082.4) ; U4.49@1251.53,1846.14 1251.53,1906.07 v1(1251.9,1906.45) ; U4.14@1290.9,2363.86 1290.9,2311.2 v1(1291.6,2310.5) ; v1@1389.32,2311.2 U4.19@1389.32,2363.86
  BOTTOM w19: C13.2@622,1965 v1(652,1935)
  BOTTOM w20: v1(392.3,2324.7) 393.61,2326.01 D4.2@475,2326.01 ; v1(424,1901) C1.1@424,1952.5 ; v1(474.2,2402.3) 475,2401.5 D4.2@475,2326.01 ; v1(493.77,1497.47) C5.2@552,1497.47 ; v1(515.1,1399.4) 538.26,1422.56 C9.1@576,1422.56 ; v1(553.5,2329.1) 478.09,2329.1 D4.2@475,2326.01 ; C17.1@612,2120 659.9,2120 v1(661.7,2121.8) ; C14.2@612,2206 C14.2@612,2205.57 612,2166.7 v1(613,2165.7) ; C16.2@876,2475.56 v1(876,2515.5) ; C3.1@913,1385.44 962.14,1385.44 v1(962.6,1385.9) ; v1(1001.1,1643.7) 1002,1644.6 C15.1@1002,1687.44 ; v1@1177.3,2562.4 Q1.2@1221.34,2562.4 ; v1(1192.7,2504) 1194.14,2502.56 C19.1@1232,2502.56 ; C12.1@1235.6,2771.06 v1(1235.6,2812.9) ; v1@1262,1644 C20.1@1262,1687.44 ; v1(1272.7,2878.6) C4.1@1325.9,2878.6 ; v1(1331.5,2501.1) 1332.96,2502.56 C21.1@1372,2502.56 ; v1(1338.7,2571.8) C10.1@1395.1,2571.8 ; v1(1351.3,2758.6) 1351.8,2758.1 U2.2@1351.8,2711.36 ; v1(1471.4,2562.4) 1472,2561.8 C18.1@1472,2520.43 C18.1@1472,2520 ; VccEXT.3@1638.5,2934 1639.5,2935 v1(1639.5,2795) ; v1(1739.74,2522.26) D5.2@1814,2522.26 v1(1814,2442.6) ; v1(1984.5,2795) VccEXT.2@1984.5,2935 ; C6.2@2121,2745.5 v1(2121,2796.2) ; C7.1@2181,2745.5 v1(2181,2796.2) ; C8.1@2271,2745.5 v1(2271,2796.2) ; v1(2772,1632.5) OUTP.4@2892,1632.5 ; v1(2772,2477.5) OUTN.5@2892,2477.5 ; v1(2887,1565) OUTP.4@2887,1627.5 ; OUTN.5@2887,2482.5 v1(2887,2545) ; OUTP.5@2892,1977.5 v1(2892,2055) OUTN.4@2892,2132.5
  BOTTOM w30: C2.1@779.56,1525 810.2,1525 v1(817,1518.2)
  other v1: 1262,1643 1992,1991 1992,2020 2337,2160 1390.03,2310.5 1177.1,2562.2
  other v2: 772,1415
I2CPU: U4.42
NetC9_2: C9.2 R2.2 U1.4 | length 159.8
  BOTTOM w10: 704.41,1389.41 U1.4@726.72,1389.41
  BOTTOM w12: R2.2@652,1367.44 682.44,1367.44 704.41,1389.41
  BOTTOM w20: C9.2@576,1367.44 R2.2@652,1367.44
NetC10_2: C10.2 R6.1 SUP2REG.2 U2.1
NetC12_2: C12.2 R6.2 U2.3
NetC13_1: C13.1 U4.69 Y1.1 | length 478.7
  BOTTOM w10: C13.1@612,1894 768.01,1894 Y1.1@772,1897.99 820.99,1897.99 849,1926 849,2015.5 900.2,2066.7
  BOTTOM w12: 900.2,2066.7 908.97,2075.47 U4.69@963.14,2075.47
NetC14_1: C14.1 U4.70 Y1.2 | length 478.5
  BOTTOM w10: C14.1@612,2276 768.01,2276 Y1.2@772,2272.01 827.99,2272.01 858,2242 858,2152.4 906.05,2104.35
  BOTTOM w12: 906.05,2104.35 915.24,2095.16 U4.70@963.14,2095.16
NetC16_1: C16.1 R15.2 U4.76 | length 329.8
  BOTTOM w12: R15.2@936,2420.44 876,2420.44 876,2358 895,2339 895,2236.2 917.93,2213.27 U4.76@963.14,2213.27
NetC24_1: C24.1 OUTP.1 R27.2 | length 177.4
  TOP w13: C24.1@2714.56,1805 2757,1805 OUTP.1@2892,1805
NetC25_1: C25.1 OUTN.1 R30.1 | length 177.4
  TOP w13: C25.1@2714.56,2305 2757,2305 OUTN.1@2892,2305
NetD1_1: D1.1 R8.1 | length 79.1
  TOP w10: R8.1@2275.5,2932 R8.1@2280.53,2937.03
  TOP w15: R8.1@2280.53,2937.03 D1.1@2280.53,3009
